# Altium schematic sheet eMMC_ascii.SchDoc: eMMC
size A3; Date: Not used; ApprovedBy: Not used; CheckedBy: Not used; Author: Not used; CompanyName: STMicroelectronics; DrawnBy: Not used; Engineer: Not used; Organization: Not used; Address1: Not used; Address2: Not used; Address3: Not used; Address4: Not used; DocumentNumber: 7; Revision: Not used; SheetNumber: 7; SheetTotal: 7
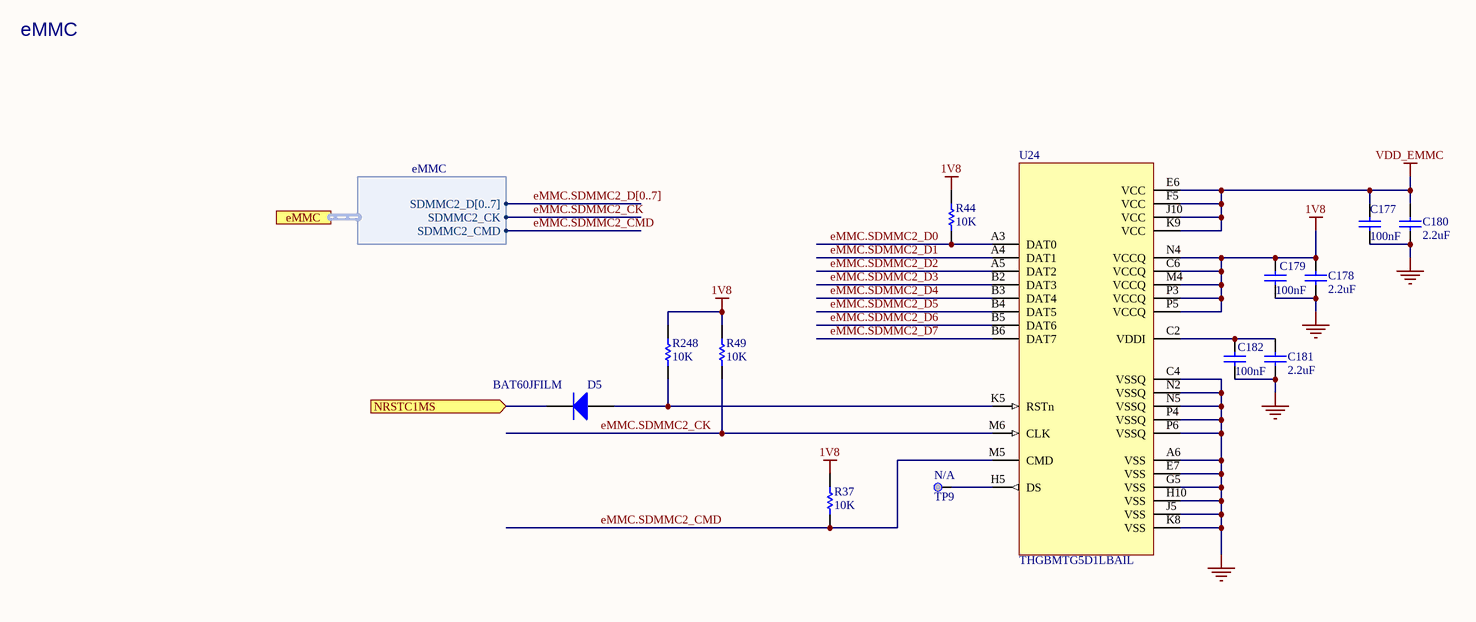
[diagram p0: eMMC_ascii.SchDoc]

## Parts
C177  value 100nF  [C0402]  (hidden comment: Capacitor)
C178  value 2.2uF  [C0402]  (hidden comment: Capacitor)
C179  value 100nF  [C0402]  (hidden comment: Capacitor)
C180  value 2.2uF  [C0402]  (hidden comment: Capacitor)
C181  value 2.2uF  [C0402]  (hidden comment: Capacitor)
C182  value 100nF  [C0402]  (hidden comment: Capacitor)
D5  BAT60JFILM  [DIO_SOD323]
R37  value 10K  [R0402]  (hidden comment: Resistor)
R44  value 10K  [R0402]  (hidden comment: Resistor)
R49  value 10K  [R0402]  (hidden comment: Resistor)
R248  value 10K  [R0402]  (hidden comment: Resistor)
TP9  Test Point  [TP_SMD_1MM]  (value not drawn)  (no BOM)
U24  value THGBMTG5D1LBAIL  [ICC_P-WFBGA153_13X11P5_P050]  (hidden comment: eMMC_THGBMTG5D1LBAIL)

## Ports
eMMC (harness eMMC), NRSTC1MS (in)

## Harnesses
eMMC: SDMMC2_CK, SDMMC2_CMD, SDMMC2_D[0..7]

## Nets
1V8: C178.2 C179.2 R37.2 R44.2 R49.2 R248.2 U24.C6(VCCQ) U24.M4(VCCQ) U24.N4(VCCQ) U24.P3(VCCQ) U24.P5(VCCQ)
GND: C177.1 C178.1 C179.1 C180.1 C181.1 C182.1 U24.A6(VSS) U24.C4(VSSQ) U24.E7(VSS) U24.G5(VSS) U24.H10(VSS) U24.J5(VSS) U24.K8(VSS) U24.N2(VSSQ) U24.N5(VSSQ) U24.P4(VSSQ) U24.P6(VSSQ)
VDD_EMMC: C177.2 C180.2 U24.E6(VCC) U24.F5(VCC) U24.J10(VCC) U24.K9(VCC)
eMMC.SDMMC2_CK: R49.1 U24.M6(CLK) ; port eMMC.SDMMC2_CK
eMMC.SDMMC2_CMD: R37.1 U24.M5(CMD) ; port eMMC.SDMMC2_CMD
eMMC.SDMMC2_D0: R44.1 U24.A3(DAT0)
eMMC.SDMMC2_D1: U24.A4(DAT1)
eMMC.SDMMC2_D2: U24.A5(DAT2)
eMMC.SDMMC2_D3: U24.B2(DAT3)
eMMC.SDMMC2_D4: U24.B3(DAT4)
eMMC.SDMMC2_D5: U24.B4(DAT5)
eMMC.SDMMC2_D6: U24.B5(DAT6)
eMMC.SDMMC2_D7: U24.B6(DAT7)
NRSTC1MS: D5.2(K) ; port NRSTC1MS
NetC181_2: C181.2 C182.2 U24.C2(VDDI)
NetD5_1: D5.1(A) R248.1 U24.K5(RSTn)
NetTP9_1: TP9.1 U24.H5(DS)

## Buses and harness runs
bus eMMC.SDMMC2_D[0..7]

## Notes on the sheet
- eMMC

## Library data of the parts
C177 C179 C182 = MCD-00006: Capacitor, MLCC, 100nF, 16V, X7R, +/-10%, 0402, T=0.5mm; Part_Preference: Recommended; Manufacturer: YAGEO; Manufacturer_Part_Number: CC0402KRX7R7BB104; Alternate_Manufacturer: MURATA; Alternate_Manufacturer_Part_Number: GCM155R71C104KA55D; Partial_Alternate_Internal_Part_Number: MCD-03299; Order_Code_RS: 9402047; Component_Country_Of_Origin: China; ID: 2474; ShowFields: YES
C178 C180 C181 = MCD-02606: Capacitor, MLCC, 2.2uF, 6.3V, X5R, +/-10%, 0402, T=0.5mm; Part_Preference: Recommended; Manufacturer: YAGEO; Manufacturer_Part_Number: CC0402KRX5R5BB225; Order_Code_RS: 1992205; ShowFields: YES; ID: 4712; Component_Country_Of_Origin: China°
D5 = MCD-00034: BMS_Part_Number: 9151097; Part_Type: Diode; Part_Preference: Recommended; Manufacturer: STMICROELECTRONICS; Manufacturer_HQ_COO: EU; Component_Country_Of_Origin: China; ShowFields: YES; ID: 2483; Order_Code_RS: 714-6879
R37 R44 R49 R248 = MCD-00053: Resistor,10K,0402,1%,1/16W; Manufacturer_Part_Number: RC0402FR-0710KL; Manufacturer: YAGEO; BMS_Part_Number: 9131590; Part_Preference: Recommended; ECCN_US: EAR99; ECCN_EU: NEC; Provided_By: SUBCO; Order_Code_RS: 9239359; Component_Country_Of_Origin: China; ID: 2539; ShowFields: YES
TP9 = MCD-00074: Test Point 1mm; Part_Type: Misc; Part_Preference: Recommended; Component_Country_Of_Origin: Unknown; ID: 2518; ShowFields: YES
U24 = MCD-02799: Memory, eMMC, 4GB, 15nm ,WFBGA , 153 pins; Part_Type: IC; Part_Preference: Not recommended; Manufacturer: KIOXIA; ShowFields: YES; ID: 4911; Component_Country_Of_Origin: Unknown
